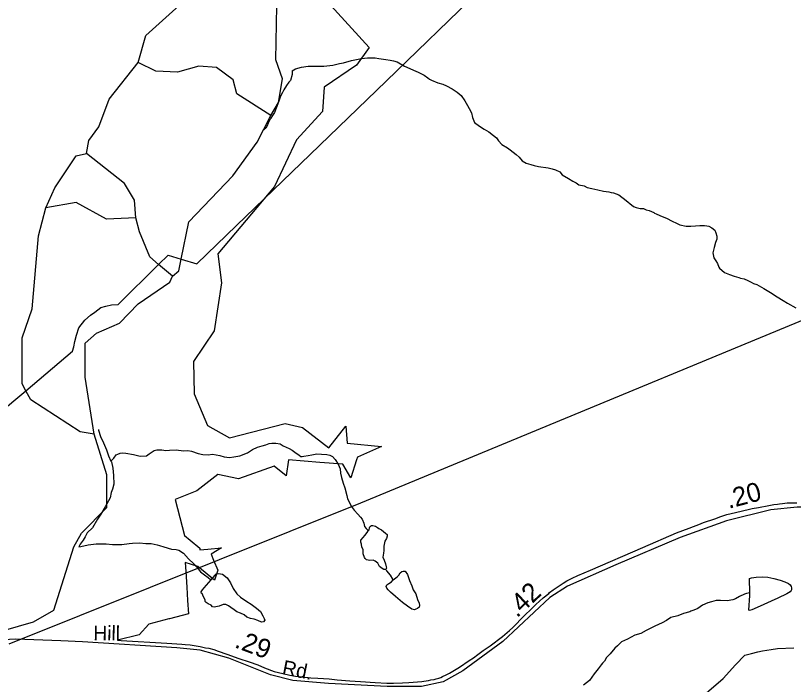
# Model space of a CAD drawing. Extents: x 2001466 to 2224147, y 644118 to 847247.
# Drawn here: x 2032407 to 2037534, y 693236 to 697641 of the extents above; entities that cross this region are included whole.
import ezdxf

# ---------------------------------------------------------------- set-up
doc = ezdxf.new("R2010")
doc.units = 0
for name, color, linetype in [('Exist Boundary Political City Limit New', 7, 'Continuous'), ('Exist Hydrographic Creek Single Shore', 7, 'Continuous'), ('Exist Hydrographic Misc Water Feature', 7, 'Continuous'), ('Exist Road Non-System Type 51', 7, 'Continuous'), ('Exist Road Secondary Mileage Hundredths English Label', 7, 'Continuous'), ('Exist Road Secondary Type 51 Attributed', 7, 'Continuous'), ('Exist Road Secondary Type 51 Label', 7, 'Continuous'), ('Exist Utilities Electrical Transmission Line', 7, 'Continuous'), ('Map Preparation Boundary City Limit Buffer Line', 7, 'Continuous')]:
    doc.layers.add(name, color=color, linetype=linetype)

msp = doc.modelspace()

# ---------------------------------------------------------------- linework, layer by layer
at = {"layer": 'Exist Boundary Political City Limit New'}
for points in [[(2034464, 697730.9), (2034738.1, 697430.1), (2034654.6, 697315.2), (2034441.8, 697169.4), (2034431.1, 697008.8), (2034258.8, 696822.1), (2034114.5, 696514.2), (2033739.5, 696072.4), (2033765.1, 695881.1)], [(2033765.1, 695881.1), (2033716.8, 695563.7), (2033580.5, 695363.7), (2033585.5, 695148.8), (2033673, 694940.3), (2033817.4, 694860.5), (2034183.4, 694955.1), (2034298.2, 694927.7), (2034470.8, 694795.2), (2034583.1, 694936.5), (2034593.1, 694824.8), (2034819.2, 694802.5), (2034660.4, 694732.4), (2034655, 694715.1), (2034617.9, 694596.7), (2034564.6, 694687.1), (2034412.1, 694698.1), (2034207.2, 694714.1), (2034190.4, 694608.9), (2034111, 694674.3), (2033876, 694589.8), (2033740.4, 694618.2), (2033602.1, 694511.2), (2033459.8, 694453.1), (2033521, 694217.2), (2033558.8, 694186.6), (2033621.8, 694133.1), (2033622.8, 694123.4), (2033673.6, 694127.8), (2033765, 694136.7), (2033696.5, 694093.8), (2033712.4, 694055.4), (2033739.6, 693989.1), (2033717.5, 693922.9), (2033607.8, 694013.1), (2033526.1, 694038.7), (2033529.5, 693979.1), (2033535.4, 693875.5), (2033541.4, 693789.1), (2033547.5, 693700.9), (2033421, 693668), (2033418.4, 693667.3), (2033285.4, 693631.9), (2033221.9, 693562.9), (2033080.1, 693526.9), (2033102.6, 693525.6), (2033403.9, 693508.8), (2033504.2, 693500.6), (2033525.2, 693499.6), (2033559.2, 693496.6), (2033625, 693485.9), (2033660, 693478.1), (2033682, 693473.8), (2033713.2, 693465.8), (2033742.9, 693455), (2033800.1, 693435), (2033878.9, 693407.9), (2033947.2, 693385.6), (2034003.5, 693364.5), (2034048.2, 693344.8), (2034112.6, 693321.4), (2034168.6, 693307.3), (2034214.2, 693297), (2034252, 693290.2), (2034292.5, 693285.8), (2034352.6, 693280.6), (2034398.9, 693277), (2034474.9, 693272.1), (2034527, 693267.4), (2034609.9, 693259.4), (2034681.1, 693255.6), (2034777.5, 693248.8), (2034854.6, 693244.7), (2034898.9, 693245.1), (2034956.6, 693246.3), (2035000, 693247.8), (2035084.1, 693254.8), (2035097.5, 693257.2), (2035129.4, 693261.6), (2035144.9, 693265.7), (2035166.9, 693269.5), (2035179.6, 693273.2), (2035196.2, 693277.6), (2035209, 693281.8), (2035221.8, 693287.6), (2035244.6, 693299), (2035266.8, 693310.8), (2035288.1, 693322.6), (2035332.4, 693348.9), (2035397.4, 693392.8), (2035425.5, 693410.8), (2035454.1, 693432.7), (2035490, 693459.4), (2035534, 693491), (2035615.9, 693552.2), (2035662.8, 693591.6), (2035685.5, 693611.7), (2035705.9, 693632.2), (2035737.8, 693666.8), (2035762.2, 693690.1)], [(2035762.2, 693690.1), (2035808, 693734.5), (2035836.8, 693762.6), (2035883.9, 693805.3), (2035920.9, 693835.8), (2035926.4, 693840.8), (2035950.5, 693858.4), (2036015.8, 693902.4), (2036040, 693918.1), (2036076.4, 693936.6), (2036113.2, 693953.6), (2036195.6, 693989.1), (2036540.5, 694137.8), (2036762.2, 694233.4), (2036846.1, 694264.4), (2036875.6, 694276.1), (2036910.4, 694289.4), (2036941.6, 694302.3), (2037016.1, 694327.5), (2037054.8, 694341.6), (2037095, 694354.4), (2037151.4, 694368.7), (2037243.1, 694390.1), (2037262.2, 694393.8), (2037302.8, 694401.6), (2037370.9, 694415.1), (2037404.4, 694420.3), (2037428.1, 694423.9), (2037442.4, 694425.7), (2037462.5, 694428), (2037491.5, 694431), (2037517.2, 694431), (2037557, 694432.5)]]:
    msp.add_lwpolyline(points, dxfattribs=at)
at = {"layer": 'Exist Hydrographic Creek Single Shore'}
msp.add_line((2033441.4, 695923.8), (2033350.4, 696001.3), dxfattribs=at)
for points in [[(2033215.5, 697332.7), (2033265.3, 697508.9), (2033681.3, 697884.3), (2033815.4, 698091.5), (2033823.4, 698160.3), (2034114.4, 698541.4)], [(2034090.4, 696983.5), (2034140.5, 697067.7), (2034165.5, 697224.8), (2034123.4, 697350.2), (2034131.4, 697825.9), (2034223.3, 697984.8), (2034223.5, 698375.2), (2034206.5, 698500.3)], [(2032874.5, 696732.6), (2032890.5, 696817.6), (2032957.3, 696908.1), (2033024.4, 697090.5), (2033215.5, 697332.7)], [(2034090.4, 696983.5), (2033865.3, 697125.9), (2033840.5, 697218.2), (2033732.4, 697299.2), (2033615.3, 697308.1), (2033474.4, 697268.4), (2033332.3, 697274.6), (2033215.5, 697332.7)], [(2033499.3, 696037.5), (2033549.3, 696282.5), (2033840.3, 696585), (2033999.4, 696808.2), (2034090.4, 696983.5)], [(2032607.3, 696373.8), (2032666.3, 696507.2), (2032807.4, 696717.6), (2032874.5, 696732.6)], [(2033199.3, 696309.3), (2033191.3, 696424.4), (2033124.4, 696534), (2032874.5, 696732.6)], [(2033199.3, 696309.3), (2033007.3, 696300.1), (2032807.4, 696409.2), (2032607.3, 696373.8)], [(2032475, 695170.5), (2032450.4, 695215.6), (2032450.4, 695517.5), (2032516.4, 695709.7), (2032558.3, 696191.2), (2032607.3, 696373.8)], [(2033350.4, 696001.3), (2033291.3, 696051.6), (2033224.3, 696216.9), (2033199.3, 696309.3)], [(2033441.4, 695923.8), (2033483.3, 695959.1), (2033499.3, 696037.5)], [(2032925.3, 694884.3), (2032866.3, 695259.6), (2032866.3, 695482.7), (2032941.3, 695550.1), (2033091.4, 695615.9), (2033216.3, 695741.4), (2033424.4, 695884.7), (2033441.4, 695923.8)], [(2032925.3, 694884.3), (2032833.2, 694899.4), (2032508.2, 695109.4), (2032475, 695170.5)], [(2031493.2, 693433.8), (2031651.3, 693440.4), (2031893.3, 693383), (2032030.3, 693404), (2032159, 693521.9), (2032243.2, 693566.5), (2032526.3, 693649), (2032659.4, 693725), (2032792.2, 694142.3), (2032842.3, 694233.1), (2033008.4, 694400.4), (2033008.4, 694616.9), (2032925.3, 694884.3)]]:
    msp.add_lwpolyline(points, dxfattribs=at)
at = {"layer": 'Exist Hydrographic Misc Water Feature'}
for points in [[(2034230.5, 697277.8), (2034252.4, 697289.8), (2034292.4, 697301.8), (2034336.3, 697307.9), (2034394.3, 697307.9), (2034438.2, 697307.9), (2034498.3, 697313.9), (2034542.1, 697326), (2034568.2, 697329.9), (2034620.3, 697343.9), (2034688.1, 697358), (2034726.3, 697362.1), (2034776.3, 697362.1), (2034802.2, 697358.1), (2034848.3, 697352.1), (2034876.2, 697348.1), (2034898.3, 697342.2), (2034922.3, 697336.2), (2034970.3, 697308.2), (2035006.2, 697292.3), (2035030.2, 697282.2), (2035060.3, 697268.3), (2035100.3, 697248.3), (2035124.3, 697230.3), (2035136.2, 697222.3), (2035148.3, 697214.4), (2035190.3, 697198.4), (2035222.3, 697188.4), (2035248.1, 697178.4), (2035284.2, 697158.4), (2035318.3, 697136.5), (2035344.3, 697114.5), (2035368.3, 697078.5), (2035386.3, 697048.5), (2035396.4, 697028.5), (2035412.4, 697000.5), (2035418.3, 696970.5), (2035432.3, 696936.6), (2035464.3, 696912.5), (2035496.3, 696892.6), (2035526.4, 696874.6), (2035556.3, 696850.7), (2035576.4, 696834.6), (2035590.4, 696816.7), (2035612.3, 696792.7), (2035648.4, 696770.7), (2035666.5, 696756.7), (2035706.4, 696726.7), (2035726.5, 696708.8), (2035746.4, 696684.8), (2035772.5, 696668.8), (2035802.4, 696660.8), (2035824.5, 696652.9), (2035854.5, 696646.9), (2035916.4, 696638.9), (2035944.5, 696630.9), (2035966.4, 696624.9), (2035994.5, 696610.9), (2036010.5, 696593), (2036050.5, 696567), (2036080.5, 696551.1), (2036102.4, 696539.1), (2036120.4, 696527.1), (2036154.5, 696519.1), (2036174.4, 696509.1), (2036204.5, 696501.1), (2036244.5, 696493.1), (2036282.4, 696485.2), (2036298.4, 696483.2), (2036316.5, 696479.2), (2036332.5, 696475.2), (2036348.5, 696473.2), (2036382.5, 696461.2), (2036402.4, 696445.3), (2036420.4, 696431.3), (2036444.4, 696411.3), (2036454.5, 696403.3), (2036480.5, 696383.3), (2036496.5, 696377.3), (2036524.4, 696371.3), (2036544.5, 696369.3), (2036562.5, 696361.4), (2036582.4, 696357.4), (2036614.4, 696343.4), (2036618.5, 696339.4), (2036628.3, 696335.4), (2036652.5, 696323.5), (2036678.6, 696313.5), (2036696.4, 696307.5), (2036734.6, 696287.5), (2036762.7, 696273.5), (2036784.6, 696263.5), (2036826.6, 696253.6), (2036858.4, 696253.6), (2036888.4, 696255.6), (2036916.4, 696257.6), (2036948.4, 696257.6), (2036962.4, 696255.6), (2036976.5, 696253.6), (2036996.4, 696243.6)], [(2034230.5, 697277.8), (2034230.5, 697271.8), (2034230.5, 697253.8), (2034218.4, 697213.8), (2034208.3, 697201.7), (2034192.3, 697179.7), (2034174.3, 697151.7), (2034166.5, 697133.8), (2034152.6, 697109.8), (2034142.5, 697077.8), (2034128.6, 697041.7), (2034114.4, 697001.7), (2034100.5, 696981.7), (2034090.6, 696965.7), (2034084.7, 696955.7)], [(2034084.7, 696955.7), (2034080.6, 696951.7), (2034072.6, 696931.7), (2034064.6, 696915.7), (2034056.6, 696899.7), (2034048.6, 696893.7), (2034042.6, 696887.7)], [(2036996.4, 696243.6), (2037016.5, 696227.6), (2037022.7, 696209.6), (2037028.6, 696187.7), (2037028.6, 696167.7), (2037020.6, 696145.7), (2037010.6, 696113.7), (2037006.5, 696095.7), (2037002.6, 696077.7), (2037008.5, 696045.7), (2037022.7, 696025.7), (2037032.7, 696007.7), (2037042.8, 695983.8), (2037046.7, 695978), (2037078.8, 695947.9), (2037113.1, 695936.5), (2037143.2, 695924.9), (2037173.4, 695916.6), (2037185.3, 695910.9), (2037209.3, 695907.1)], [(2037209.3, 695907.1), (2037233.3, 695897.1), (2037255.4, 695885.2), (2037271.4, 695877.2), (2037291.3, 695869.2), (2037307.3, 695861.3), (2037339.5, 695843.3), (2037383.4, 695817.4), (2037427.4, 695789.4), (2037465.6, 695763.6), (2037493.5, 695747.6), (2037549.6, 695715.7)], [(2032954, 694915.3), (2032954, 694911.3), (2032968, 694869.3), (2032987.9, 694827.4), (2033005.9, 694781.4), (2033020, 694741.4), (2033036, 694707.4)], [(2033036, 694707.4), (2033054.1, 694725.4), (2033070.1, 694747.4), (2033082, 694753.4), (2033095.9, 694759.4), (2033114, 694761.4), (2033133.9, 694759.4), (2033183.9, 694749.5), (2033228, 694739.5), (2033270, 694741.6), (2033287.8, 694755.6), (2033319.8, 694775.6), (2033337.9, 694781.6), (2033371.9, 694781.6), (2033398, 694777.6), (2033422, 694779.6), (2033465.8, 694781.7), (2033514, 694773.7), (2033541.9, 694775.7), (2033567.9, 694771.7), (2033610, 694755.8), (2033642, 694749.8), (2033676, 694747.8), (2033705.9, 694751.8), (2033753.9, 694743.9), (2033782, 694735.9), (2033817.9, 694729.9), (2033846, 694733.9), (2033886, 694741.9), (2033935.8, 694761.9), (2033969.8, 694784), (2034001.8, 694798), (2034031.8, 694808), (2034055.8, 694814), (2034077.7, 694822), (2034095.8, 694824), (2034121.8, 694824.1), (2034151.7, 694820.1), (2034171.8, 694808.1), (2034209.8, 694790.1), (2034229.9, 694778.1), (2034247.9, 694766.1), (2034257.7, 694758.1), (2034267.8, 694752.1), (2034275.8, 694746.1), (2034287.9, 694738.1), (2034295.9, 694736.2), (2034307.8, 694738.2), (2034335.9, 694744.2), (2034359.9, 694748.2), (2034393.9, 694754.3), (2034423.8, 694752.3), (2034459.7, 694750.3), (2034477.8, 694746.3), (2034495.8, 694736.2), (2034513.9, 694718.4), (2034533.7, 694686.3), (2034545.8, 694656.3), (2034549.7, 694628.4), (2034555.9, 694598.3), (2034565.9, 694562.4), (2034577.8, 694530.4), (2034589.9, 694480.4), (2034595.9, 694458.4), (2034611.9, 694424.5), (2034619.9, 694410.5), (2034637.9, 694384.5), (2034662.1, 694358.4), (2034679.9, 694338.5), (2034691.8, 694324.5), (2034702.1, 694298.5), (2034708, 694276.5), (2034718.1, 694262.5), (2034728.1, 694252.5), (2034732, 694248.5)], [(2033036, 694707.4), (2033040.1, 694701.4), (2033048.1, 694659.5), (2033052, 694611.4), (2033054.1, 694555.4), (2033046.1, 694521.5), (2033038.1, 694499.4), (2033030.1, 694465.4), (2032998.1, 694405.4), (2032970.2, 694357.4), (2032948.3, 694323.4), (2032914.2, 694267.4), (2032880.2, 694233.4), (2032866.3, 694207.4), (2032852.5, 694185.4), (2032832.4, 694159.4), (2032824.4, 694143.3)], [(2034732, 694248.5), (2034738, 694254.5), (2034740, 694266.5), (2034742.1, 694274.5), (2034746, 694278.5), (2034752.1, 694282.5), (2034762, 694282.6), (2034780, 694278.5), (2034792.1, 694270.6), (2034802, 694262.6), (2034817.9, 694254.6), (2034846, 694232.6), (2034856.1, 694222.6), (2034856.1, 694212.6), (2034852, 694196.6), (2034840.1, 694178.6), (2034833.9, 694146.6), (2034833.9, 694118.6), (2034832.1, 694100.6), (2034828.2, 694074.6), (2034836.2, 694054.7), (2034846.2, 694030.7), (2034850.1, 694010.7), (2034852.2, 694000.7), (2034848.1, 693992.7)], [(2034848.1, 693992.7), (2034834.1, 693992.7), (2034824.1, 693998.7), (2034806.1, 694012.7), (2034800.1, 694026.7), (2034794.2, 694034.7), (2034778.2, 694048.6), (2034764.2, 694054.6), (2034742.1, 694052.6), (2034720.1, 694056.6), (2034712.1, 694064.5), (2034706.2, 694072.5), (2034698.2, 694096.5), (2034698, 694124.5), (2034690, 694140.5), (2034686.1, 694160.5), (2034682, 694172.5), (2034682, 694186.5), (2034698, 694204.5), (2034710.1, 694216.5), (2034724, 694236.5), (2034732, 694248.5)], [(2032824.4, 694143.3), (2032838.4, 694143.4), (2032886.4, 694155.4), (2032938.4, 694161.4), (2033004.3, 694161.5), (2033046.3, 694157.5), (2033108.2, 694157.5), (2033156.2, 694163.5), (2033178.3, 694165.5), (2033224.3, 694167.6), (2033266.3, 694163.6), (2033302.2, 694163.6), (2033340.3, 694155.7), (2033356.3, 694151.7), (2033384.2, 694141.7), (2033434.3, 694125.8), (2033466.2, 694123.8), (2033484.3, 694119.8), (2033514.2, 694099.8), (2033546.2, 694063.8), (2033582.3, 694029.9), (2033604.4, 694005.9), (2033626.4, 693977.9), (2033652.4, 693957.9), (2033676.4, 693939.9), (2033692.4, 693927.9), (2033696.3, 693923.9)], [(2034848.1, 693992.7), (2034852.2, 693984.6), (2034876.2, 693954.6), (2034892.2, 693928.6), (2034896.1, 693924.7)], [(2034896.1, 693924.7), (2034904.1, 693930.7), (2034922.1, 693944.7), (2034934.2, 693956.7), (2034942.2, 693970.7), (2034952, 693978.7), (2034962.1, 693982.7), (2034974.2, 693982.7), (2034990.2, 693960.7), (2035004.1, 693920.8), (2035018.1, 693884.8), (2035028.1, 693858.8), (2035044.3, 693832.8), (2035056.2, 693794.8), (2035066.3, 693770.8), (2035068.3, 693756.9), (2035066.3, 693744.8), (2035056.2, 693736.8), (2035046.2, 693730.8), (2035036.3, 693726.8), (2035018.3, 693732.8), (2034990.2, 693750.8), (2034956.4, 693774.7), (2034912.3, 693814.7), (2034878.2, 693844.6), (2034862.2, 693858.7), (2034854.2, 693870.7), (2034850.1, 693880.7), (2034854.2, 693892.7), (2034868.2, 693900.7), (2034884.2, 693912.7), (2034896.1, 693924.7)], [(2033696.3, 693923.9), (2033722.4, 693955.9), (2033728.3, 693964), (2033744.5, 693966), (2033772.2, 693962), (2033802.3, 693938), (2033824.5, 693906), (2033840.5, 693868), (2033866.3, 693832.1), (2033890.5, 693810.1), (2033930.5, 693782.1), (2033960.4, 693764.1), (2033994.5, 693738.2), (2034022.3, 693716.2), (2034036.5, 693688.2), (2034046.5, 693670.2), (2034050.4, 693658.2), (2034042.4, 693648.2), (2034028.5, 693646.2), (2034004.5, 693656.2), (2033980.5, 693666.1), (2033956.5, 693670.1), (2033932.5, 693680.1), (2033914.5, 693694.1), (2033890.5, 693706.1), (2033866.3, 693714.1), (2033848.5, 693728.1), (2033826.5, 693742.1), (2033810.3, 693754), (2033792.5, 693762), (2033776.5, 693762), (2033748.4, 693752), (2033726.5, 693746), (2033716.6, 693745.9), (2033704.5, 693747.9), (2033696.5, 693757.9), (2033676.4, 693765.9), (2033662.5, 693775.9), (2033656.5, 693781.9), (2033656.3, 693793.9), (2033646.5, 693813.9), (2033636.4, 693834), (2033632.3, 693835.9), (2033630.5, 693846), (2033640.3, 693860), (2033650.4, 693872), (2033696.3, 693923.9)], [(2037245.1, 693839.5), (2037242.9, 693933.5), (2037256.8, 693937.5), (2037287, 693943.5), (2037327, 693943.6), (2037364.9, 693941.6), (2037404.9, 693933.7), (2037446.9, 693921.8), (2037476.9, 693911.9), (2037501.1, 693899.9), (2037512.9, 693891.9), (2037519.1, 693881.9), (2037520.9, 693872), (2037520.9, 693866), (2037520.9, 693860), (2037519.1, 693854), (2037512.9, 693846), (2037489.2, 693831.9), (2037431.1, 693803.8), (2037387, 693783.7), (2037315.3, 693751.6), (2037259.3, 693727.5), (2037243.3, 693723.4), (2037239.2, 693725.4), (2037245.1, 693821.5), (2037245.1, 693839.5)], [(2037211.1, 693829.4), (2037179.1, 693815.5), (2037151.2, 693799.9), (2037133.4, 693792.2), (2037097.7, 693787), (2037051.8, 693787.9), (2037023.9, 693788.1), (2036994, 693780), (2036970, 693774), (2036934.1, 693758), (2036903.9, 693736), (2036877.9, 693726), (2036858, 693718), (2036850, 693714), (2036808, 693704), (2036772.1, 693687.9), (2036726, 693677.9), (2036696, 693657.8), (2036667.9, 693641.8), (2036619.9, 693619.8), (2036594.1, 693605.8), (2036562.1, 693591.8), (2036528.1, 693571.8), (2036488.1, 693559.8), (2036440.1, 693533.7), (2036400.1, 693515.7), (2036374.1, 693489.7), (2036356, 693475.7), (2036326.3, 693437.7), (2036302.3, 693413.6), (2036288.2, 693389.7), (2036276.3, 693375.7), (2036266.2, 693365.6), (2036246.3, 693339.6), (2036220.3, 693305.6), (2036190.4, 693261.6), (2036150.4, 693231.6)], [(2037245.1, 693839.5), (2037225.1, 693835.4), (2037211.1, 693829.4)]]:
    msp.add_lwpolyline(points, dxfattribs=at)
at = {"layer": 'Exist Road Non-System Type 51'}
msp.add_lwpolyline([(2035564.2, 690800.7), (2036399, 692489.7), (2036444.9, 692553.8), (2036509, 692635.9), (2036550.8, 692703.8), (2036609, 692779.9), (2036634.9, 692823.9), (2036670.8, 692887.8), (2036714.8, 692949.9), (2036762.7, 693004), (2036816.7, 693049.9), (2036870.7, 693102), (2036976.6, 693194), (2037070.7, 693276.1), (2037152.6, 693366.1), (2037212.5, 693428.1), (2037257.7, 693439.1), (2037297.9, 693450.3), (2037330.1, 693457.7), (2037386.3, 693466.5), (2037428.4, 693471.7), (2037536.5, 693477.5)], dxfattribs=at)
at = {"layer": 'Exist Road Secondary Type 51 Attributed'}
for points in [[(2038786.2, 694537.2), (2038720.8, 694490.7), (2038632.1, 694445.3), (2038545, 694421), (2038386.7, 694404.1), (2037558, 694403), (2037384.9, 694385.1), (2037093, 694314.3), (2036787.9, 694203.4), (2036363.1, 694023.8), (2036044.3, 693882.2), (2035928.1, 693808.3), (2035618.8, 693518.9), (2035355.5, 693325.5), (2035224.6, 693253.7), (2035083.1, 693222), (2034857.2, 693222), (2034469.8, 693242.1), (2034235.4, 693262.2), (2034087.1, 693300.2), (2033812.7, 693410), (2033624.8, 693460.8), (2033470.6, 693477.7), (2032848.5, 693515.5)], [(2032848.5, 693515.5), (2032706.4, 693524.1), (2032408.5, 693534.8), (2032282.8, 693527.9), (2032159, 693521.9)]]:
    msp.add_lwpolyline(points, dxfattribs=at)
at = {"layer": 'Exist Utilities Electrical Transmission Line'}
msp.add_line((2032263.3, 694992.5), (2032475, 695170.5), dxfattribs=at)
for points in [[(2033499.3, 696037.5), (2033602, 696006.1), (2033863.4, 696258.6), (2034348.3, 696725.8), (2034849, 697209), (2035467.7, 697808.5), (2036175.9, 698510.3), (2037148.1, 699464.1)], [(2032364.5, 693503.1), (2034681.8, 694431.6), (2038664.9, 696078), (2040380.3, 696785.9)], [(2033350.4, 696001.3), (2033413.9, 696063.6), (2033499.3, 696037.5)], [(2032475, 695170.5), (2032783.4, 695429.9), (2032791.4, 695460), (2032797.3, 695494.1), (2032809.1, 695536), (2032825.1, 695584.1), (2032864.9, 695634.1), (2032900.8, 695668.2), (2032928.9, 695688.4), (2032968.7, 695718.4), (2033002.6, 695726.5), (2033040.6, 695736.5), (2033082.7, 695738.7), (2033350.4, 696001.3)]]:
    msp.add_lwpolyline(points, dxfattribs=at)
at = {"layer": 'Map Preparation Boundary City Limit Buffer Line'}
for points in [[(2034464, 697730.9), (2034738.1, 697430.1), (2034654.6, 697315.2), (2034441.8, 697169.4), (2034431.1, 697008.8), (2034258.8, 696822.1), (2034114.5, 696514.2), (2033739.5, 696072.4), (2033765.1, 695881.1)], [(2033765.1, 695881.1), (2033716.8, 695563.7), (2033580.5, 695363.7), (2033585.5, 695148.8), (2033673, 694940.3), (2033817.4, 694860.5), (2034183.4, 694955.1), (2034298.2, 694927.7), (2034470.8, 694795.2), (2034583.1, 694936.5), (2034593.1, 694824.8), (2034819.2, 694802.5), (2034660.4, 694732.4), (2034655, 694715.1), (2034617.9, 694596.7), (2034564.6, 694687.1), (2034412.1, 694698.1), (2034207.2, 694714.1), (2034190.4, 694608.9), (2034111, 694674.3), (2033876, 694589.8), (2033740.4, 694618.2), (2033602.1, 694511.2), (2033459.8, 694453.1), (2033521, 694217.2), (2033558.8, 694186.6), (2033621.8, 694133.1), (2033622.8, 694123.4), (2033673.6, 694127.8), (2033765, 694136.7), (2033696.5, 694093.8), (2033712.4, 694055.4), (2033739.6, 693989.1), (2033717.5, 693922.9), (2033607.8, 694013.1), (2033526.1, 694038.7), (2033529.5, 693979.1), (2033535.4, 693875.5), (2033541.4, 693789.1), (2033547.5, 693700.9), (2033421, 693668), (2033418.4, 693667.3), (2033285.4, 693631.9), (2033221.9, 693562.9), (2033080.1, 693526.9), (2033102.6, 693525.6), (2033403.9, 693508.8), (2033504.2, 693500.6), (2033525.2, 693499.6), (2033559.2, 693496.6), (2033625, 693485.9), (2033660, 693478.1), (2033682, 693473.8), (2033713.2, 693465.8), (2033742.9, 693455), (2033800.1, 693435), (2033878.9, 693407.9), (2033947.2, 693385.6), (2034003.5, 693364.5), (2034048.2, 693344.8), (2034112.6, 693321.4), (2034168.6, 693307.3), (2034214.2, 693297), (2034252, 693290.2), (2034292.5, 693285.8), (2034352.6, 693280.6), (2034398.9, 693277), (2034474.9, 693272.1), (2034527, 693267.4), (2034609.9, 693259.4), (2034681.1, 693255.6), (2034777.5, 693248.8), (2034854.6, 693244.7), (2034898.9, 693245.1), (2034956.6, 693246.3), (2035000, 693247.8), (2035084.1, 693254.8), (2035097.5, 693257.2), (2035129.4, 693261.6), (2035144.9, 693265.7), (2035166.9, 693269.5), (2035179.6, 693273.2), (2035196.2, 693277.6), (2035209, 693281.8), (2035221.8, 693287.6), (2035244.6, 693299), (2035266.8, 693310.8), (2035288.1, 693322.6), (2035332.4, 693348.9), (2035397.4, 693392.8), (2035425.5, 693410.8), (2035454.1, 693432.7), (2035490, 693459.4), (2035534, 693491), (2035615.9, 693552.2), (2035662.8, 693591.6), (2035685.5, 693611.7), (2035705.9, 693632.2), (2035737.8, 693666.8), (2035762.2, 693690.1)], [(2035762.2, 693690.1), (2035808, 693734.5), (2035836.8, 693762.6), (2035883.9, 693805.3), (2035920.9, 693835.8), (2035926.4, 693840.8), (2035950.5, 693858.4), (2036015.8, 693902.4), (2036040, 693918.1), (2036076.4, 693936.6), (2036113.2, 693953.6), (2036195.6, 693989.1), (2036540.5, 694137.8), (2036762.2, 694233.4), (2036846.1, 694264.4), (2036875.6, 694276.1), (2036910.4, 694289.4), (2036941.6, 694302.3), (2037016.1, 694327.5), (2037054.8, 694341.6), (2037095, 694354.4), (2037151.4, 694368.7), (2037243.1, 694390.1), (2037262.2, 694393.8), (2037302.8, 694401.6), (2037370.9, 694415.1), (2037404.4, 694420.3), (2037428.1, 694423.9), (2037442.4, 694425.7), (2037462.5, 694428), (2037491.5, 694431), (2037517.2, 694431), (2037557, 694432.5)]]:
    msp.add_lwpolyline(points, dxfattribs=at)

# ---------------------------------------------------------------- texts
at = {"layer": 'Exist Road Secondary Mileage Hundredths English Label'}
for s, rotation, p in [('.20', 14.8091, (2037106.9, 694392.4)), ('.42', 43.2632, (2035711.4, 693670.4)), ('.29', 339.4141, (2033844.5, 693482.1))]:
    msp.add_text(s, height=125, rotation=rotation, dxfattribs=at).set_placement(p)
at = {"layer": 'Exist Road Secondary Type 51 Label'}
for s, rotation, p in [('Hill', 359.5003, (2032919.4, 693527.6)), ('Rd.', 348.6855, (2034159.9, 693304.4))]:
    msp.add_text(s, height=95, rotation=rotation, dxfattribs=at).set_placement(p)

doc.saveas('drawing.dxf')
